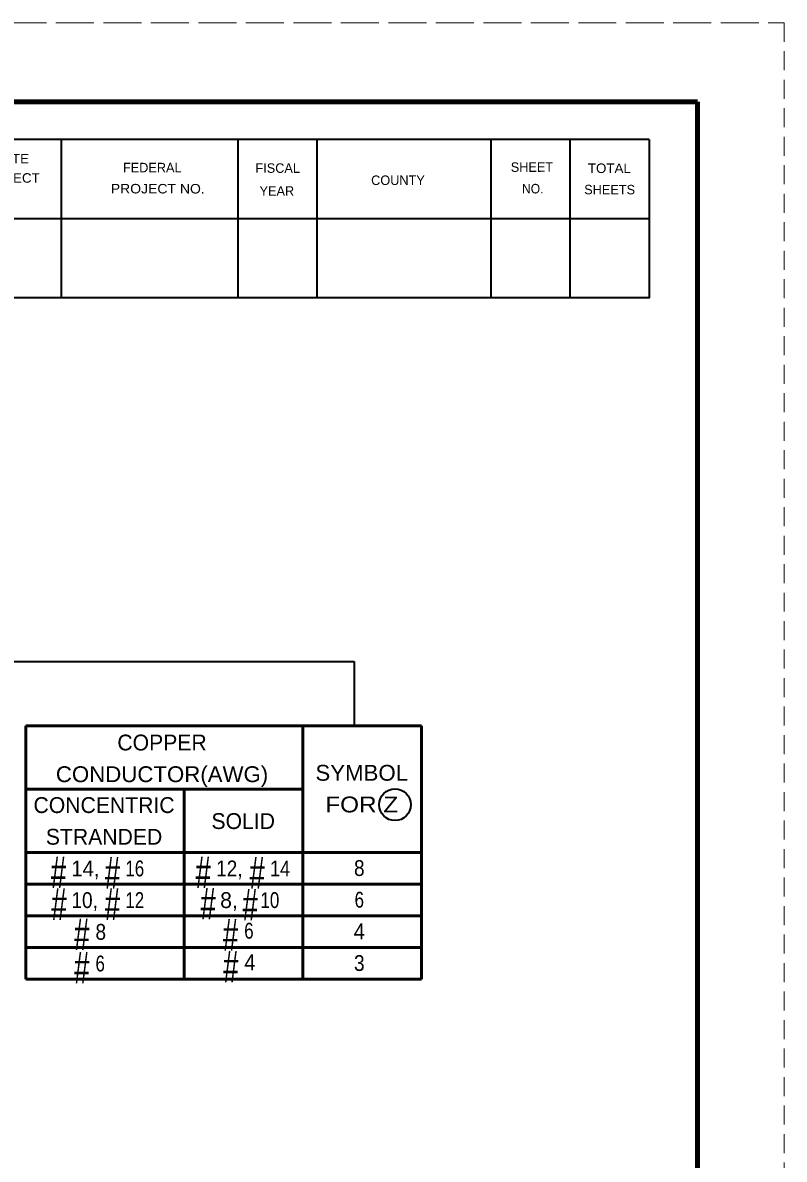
# Model space of a CAD drawing. Extents: x -1 to 679, y 0 to 440.
# Drawn here: x 582.5 to 678.7, y 296.3 to 439.9 of the extents above; entities that cross this region are included whole.
import ezdxf
from ezdxf.enums import TextEntityAlignment as Align

# ---------------------------------------------------------------- set-up
doc = ezdxf.new("R2010")
doc.units = 0
doc.header["$LTSCALE"] = 0.8
doc.linetypes.add('LONG_DASHED', pattern=[7.5, 6, -1.5])
doc.linetypes.add('MEDIUM_DASHED', pattern=[4.5, 3, -1.5])
doc.layers.add('1', color=7, linetype='Continuous', lineweight=53)
doc.layers.add('61', color=7, linetype='Continuous', lineweight=35)

msp = doc.modelspace()

# ---------------------------------------------------------------- linework, layer by layer
at = {"layer": '1', "linetype": 'MEDIUM_DASHED', "lineweight": 13}
msp.add_line((678.735, 439.9088), (678.715, -0.1112), dxfattribs=at)
at = {"layer": '1', "lineweight": 35}
for p, q in [((537.1135, 359.2272), (624.4022, 359.2272)), ((624.4022, 359.2272), (624.4022, 351.2272))]:
    msp.add_line(p, q, dxfattribs=at)
at = {"layer": '1'}
for p, q in [((582.9158, 351.0969), (582.9158, 319.0969)), ((582.9158, 351.0969), (632.9158, 351.0969)), ((617.9158, 351.0969), (617.9158, 319.0969)), ((632.9158, 351.0969), (632.9158, 319.0969)), ((582.9158, 343.0969), (617.9158, 343.0969)), ((602.9158, 343.0969), (602.9158, 319.0969)), ((582.9158, 335.0969), (632.9158, 335.0969)), ((582.9158, 331.0969), (632.9158, 331.0969)), ((582.9158, 327.0969), (632.9158, 327.0969)), ((582.9158, 323.0969), (632.9158, 323.0969)), ((582.9158, 319.0969), (632.9158, 319.0969))]:
    msp.add_line(p, q, dxfattribs=at)
at = {"layer": '1', "lineweight": 35}
msp.add_circle((629.5536, 341.112), 2, dxfattribs=at)
at = {"layer": '61', "linetype": 'LONG_DASHED', "lineweight": 13}
msp.add_line((-1.285, 439.9088), (678.735, 439.9088), dxfattribs=at)
at = {"layer": '61', "lineweight": 158}
msp.add_line((667.755, 429.9088), (667.775, 9.8688), dxfattribs=at)
at = {"layer": '61'}
for p, q in [((587.355, 425.1488), (587.355, 405.1488)), ((609.675, 425.1488), (609.675, 405.1488)), ((619.675, 425.1488), (619.675, 405.1488)), ((641.655, 425.1688), (641.655, 405.1688)), ((651.655, 425.1688), (651.655, 405.1688)), ((661.675, 415.1288), (553.655, 415.1488))]:
    msp.add_line(p, q, dxfattribs=at)
at = {"layer": '61', "lineweight": 158}
msp.add_lwpolyline([(667.755, 429.9088), (28.715, 429.9088), (28.715, 9.8888)], dxfattribs=at)
at = {"layer": '61'}
for points in [[(661.655, 425.1688), (553.675, 425.1488), (553.675, 405.1488)], [(661.655, 425.1688), (661.655, 405.1688), (553.675, 405.1488)]]:
    msp.add_lwpolyline(points, dxfattribs=at)

# ---------------------------------------------------------------- texts
at = {"layer": '1'}
for s, p in [('COPPER', (600.115, 347.9762)), ('CONCENTRIC', (592.7871, 340.0722)), ('STRANDED', (592.787, 336.0722))]:
    msp.add_text(s, height=2, dxfattribs=at).set_placement(p, align=Align.CENTER)
for s, width, p in [('CONDUCTOR(AWG)', 1.05, (600.115, 343.9762)), ('SYMBOL', 1.05, (625.348, 344.1517)), ('FOR Z', 1.15, (625.348, 340.1517)), ('8', 0.9, (625.0378, 332.1201)), ('6', 0.8, (625.0378, 328.1201)), ('4', 0.95, (625.0377, 324.1201)), ('3', 0.9, (625.0378, 320.1201))]:
    msp.add_text(s, height=2, dxfattribs=dict(at, width=width)).set_placement(p, align=Align.CENTER)
for s, p in [('SOLID', (606.3595, 338.0524)), ('8,', (607.4566, 328.0698))]:
    msp.add_text(s, height=2, dxfattribs=at).set_placement(p)
for s, height, width, p in [('#', 4, 0.65, (586.0671, 330.5901)), ('#', 4, 0.65, (604.3491, 330.5901)), ('14,', 2, 0.95, (588.6649, 332.0698)), ('#', 4, 0.65, (592.883, 330.5263)), ('16', 2, 0.8, (595.4808, 332.0698)), ('12,', 2, 0.9, (606.9469, 332.0698)), ('#', 4, 0.65, (611.165, 330.5263)), ('14', 2, 0.85, (613.7628, 332.0698)), ('#', 4, 0.65, (586.1308, 326.5757)), ('#', 4, 0.65, (592.883, 326.5756)), ('#', 4, 0.65, (604.9861, 326.6394)), ('#', 4, 0.65, (610.2732, 326.5119)), ('10,', 2, 0.9, (588.6649, 328.0698)), ('12', 2, 0.8, (595.4808, 328.0698)), ('10', 2, 0.8, (612.5525, 328.0697)), ('#', 4, 0.65, (588.9973, 322.7523)), ('8', 2, 0.9, (591.7052, 324.0582)), ('#', 4, 0.65, (607.7888, 322.6924)), ('6', 2, 0.8, (610.4968, 324.2)), ('#', 4, 0.65, (588.9973, 318.5506)), ('6', 2, 0.8, (591.7052, 320.0582)), ('#', 4, 0.65, (607.8506, 318.676)), ('4', 2, 0.95, (610.4968, 320.2))]:
    msp.add_text(s, height=height, dxfattribs=dict(at, width=width)).set_placement(p)
at = {"layer": '61'}
for s, rotation, width, p in [('STATE', 0.059, 1.05, (577.875, 422.1288)), ('TOTAL', 359.926, 1.05, (653.915, 420.9288)), ('PROJECT', 359.908, 1.05, (576.795, 419.7088)), ('PROJECT NO.', 359.922, 1.1, (593.635, 418.3488)), ('NO.', 359.852, 0.95, (645.595, 418.3488))]:
    msp.add_text(s, height=1.201, rotation=rotation, dxfattribs=dict(at, width=width)).set_placement(p)
for s, rotation, p in [('FEDERAL', 0.007, (595.175, 421.0088)), ('FISCAL', 359.942, (611.915, 420.9488)), ('SHEET', 0.059, (644.175, 421.0688)), ('YEAR', 0.105, (612.435, 418.0488)), ('COUNTY', 0.069, (626.535, 419.4088)), ('SHEETS', 359.959, (653.455, 418.2288))]:
    msp.add_text(s, height=1.201, rotation=rotation, dxfattribs=at).set_placement(p)

doc.saveas('drawing.dxf')
